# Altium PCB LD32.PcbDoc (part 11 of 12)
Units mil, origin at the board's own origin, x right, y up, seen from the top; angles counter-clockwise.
Board outline 7007.87 x 4368.85 mil, 12 copper layers (Top Layer, Int1 (GND), Int2 (AVDD), Int3 (DVDD), Int4 (GND), Int5 (ST), Int6 (SB), Int8 (AGND), Int7 (AVCC), Int9 (VCCA), Int10 (GND), Bottom Layer), stack 60.136 mil thick; 1165 components, 667 nets, 3910 pads, 2570 vias.
Unrouted connection lines stored in the file: 14.
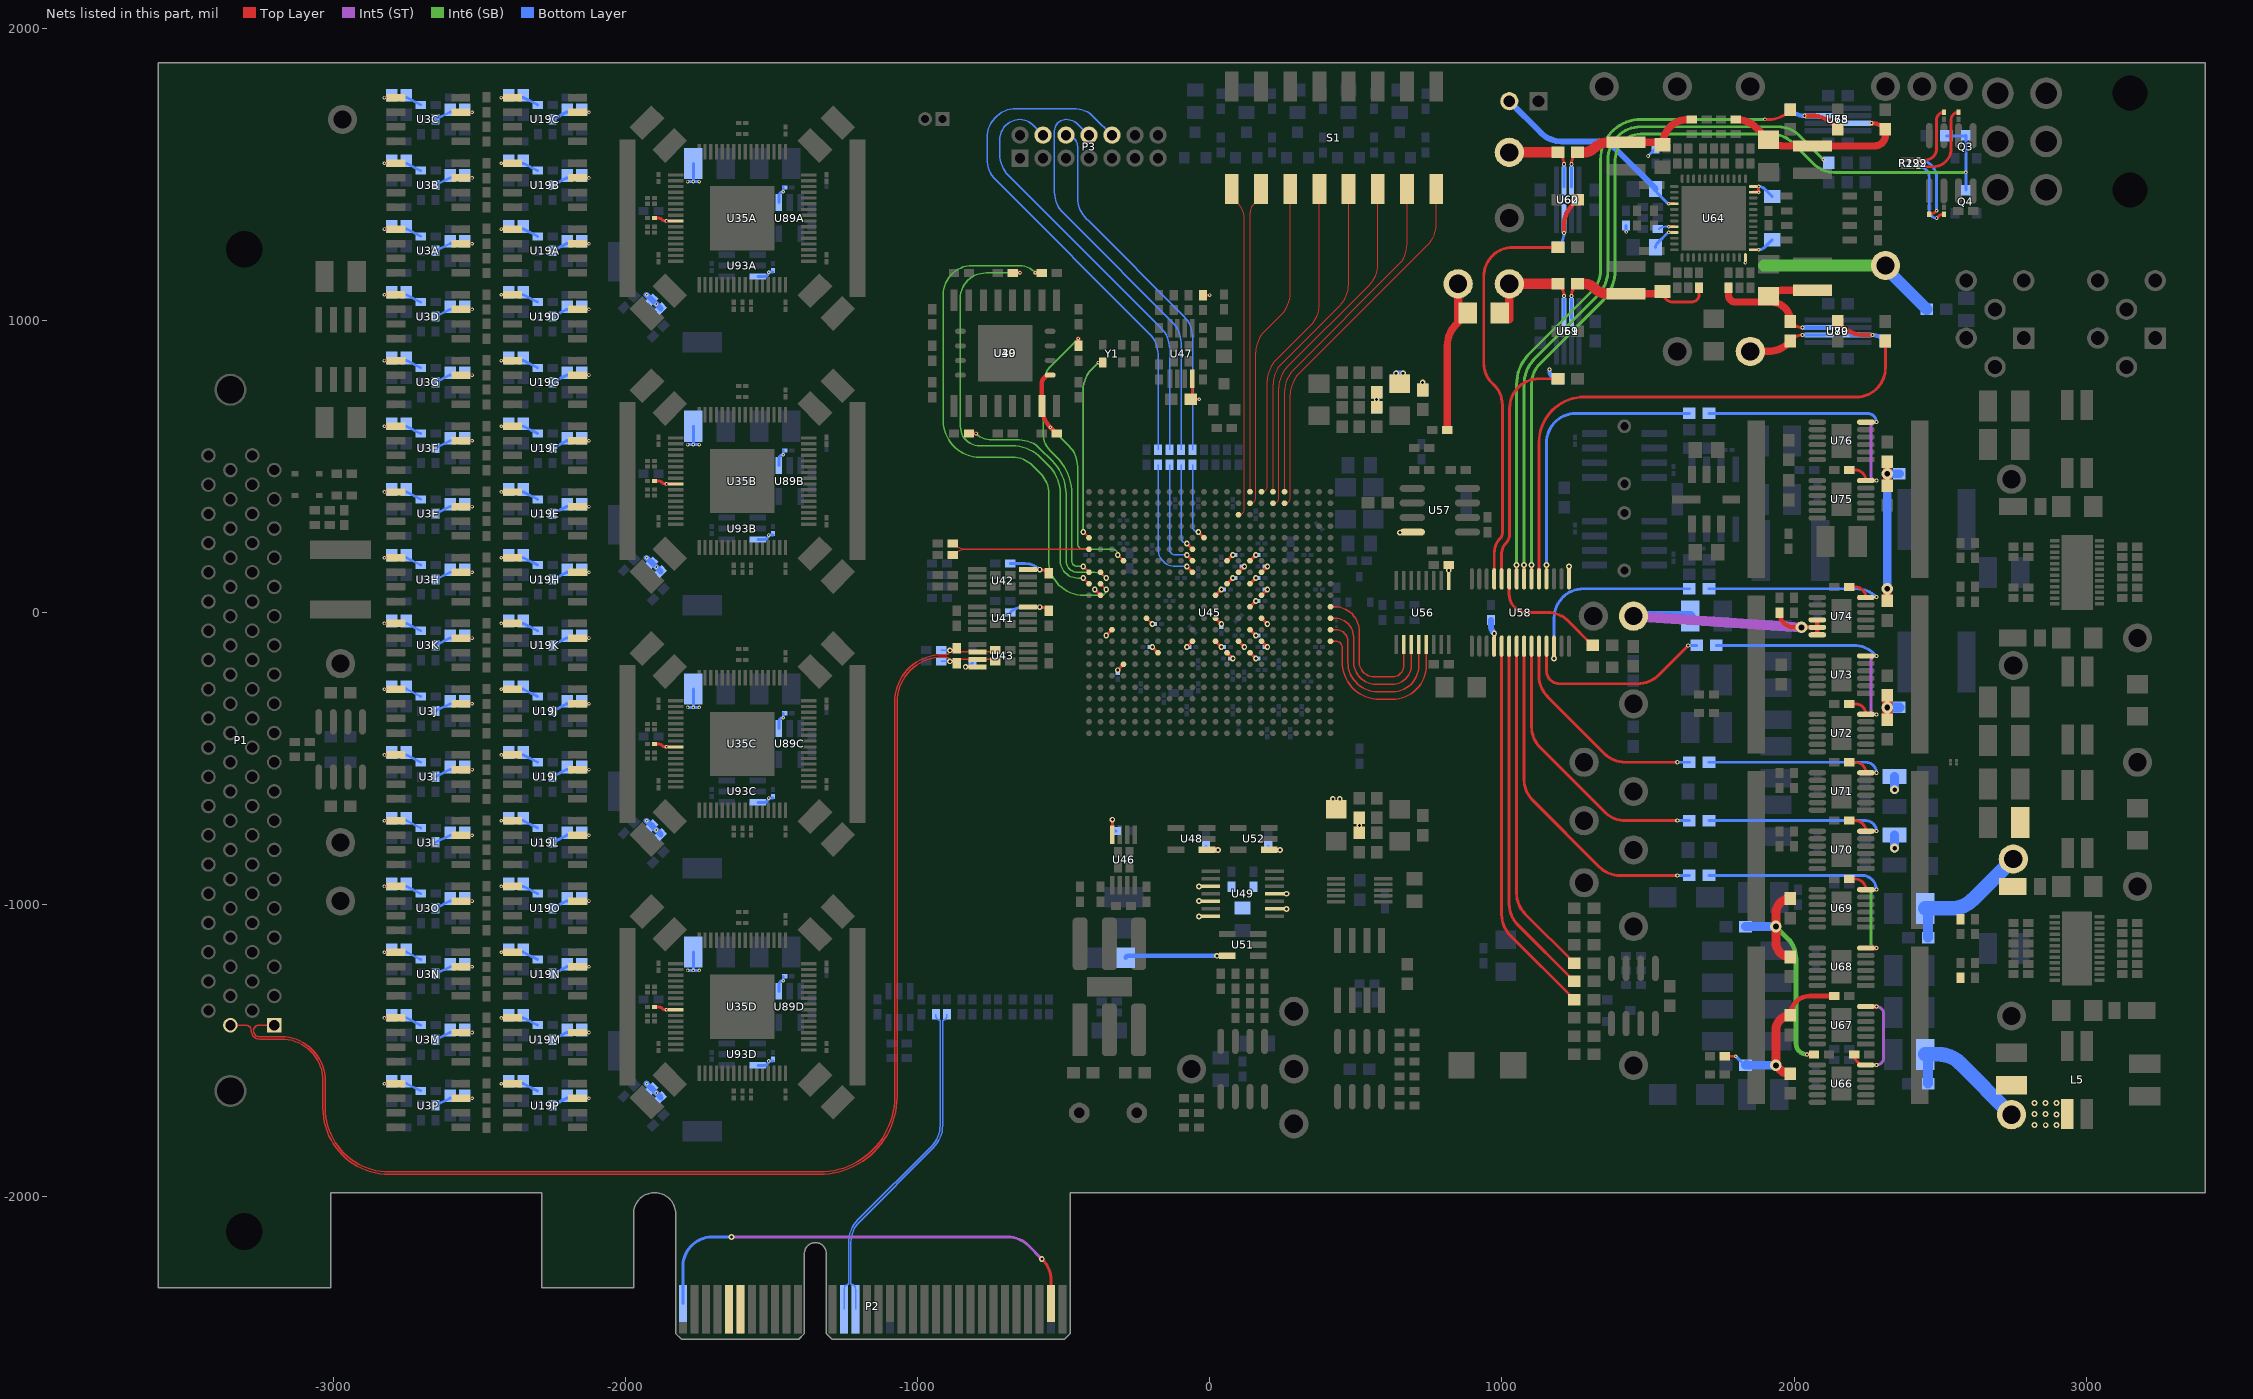
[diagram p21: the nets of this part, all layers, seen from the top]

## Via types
v1: diameter 12, hole 6, Top Layer to Bottom Layer, tented both sides, 1500 vias
v2: diameter 19, hole 10, Top Layer to Bottom Layer, tented both sides, 404 vias
v3: diameter 20, hole 10, Top Layer to Bottom Layer, tented both sides, 337 vias
v4: diameter 14, hole 7, Top Layer to Bottom Layer, tented both sides, 212 vias
v5: diameter 30, hole 15, Top Layer to Bottom Layer, tented both sides, 37 vias
v6: diameter 19.68, hole 7.87, Top Layer to Bottom Layer, 25 vias
v7: diameter 40, hole 20, Top Layer to Bottom Layer, tented both sides, 16 vias
v8: diameter 19.02, hole 10, Top Layer to Bottom Layer, tented both sides, 10 vias
v9: diameter 40, hole 20, Top Layer to Bottom Layer, 9 vias
v10: diameter 60, hole 40, Top Layer to Bottom Layer, 5 vias
v11: diameter 25, hole 13, Top Layer to Bottom Layer, 4 vias
v12: diameter 50, hole 25, Top Layer to Bottom Layer, tented both sides, 4 vias
v13: diameter 35, hole 20, Top Layer to Bottom Layer, 2 vias
v14: diameter 50, hole 25, Top Layer to Bottom Layer, 2 vias
v15: diameter 63, hole 45, Top Layer to Bottom Layer, 1 vias
v16: diameter 14.02, hole 7.01, Top Layer to Bottom Layer, tented both sides, 1 vias
v17: diameter 60, hole 40, Top Layer to Bottom Layer, tented both sides, 1 vias

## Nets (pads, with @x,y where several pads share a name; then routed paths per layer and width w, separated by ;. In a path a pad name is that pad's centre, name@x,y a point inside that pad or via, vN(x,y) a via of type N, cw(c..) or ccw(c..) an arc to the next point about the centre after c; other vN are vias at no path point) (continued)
PRSNT1#: P2.A1 P2.B31 | length 1601.4
  Top Layer w10: v3(-575,-2212.5) -572.52,-2214.98 cw(c-643.23,-2285.69) -543.23,-2285.69 P2.B31@-543.23,-2365.31
  Int5 (ST) w10: v3(-1637.5,-2137.5) -691.42,-2137.5 cw(c-691.42,-2237.5) -620.71,-2166.79 v3(-575,-2212.5)
  Bottom Layer w10: P2.A1@-1803.07,-2365.31 -1803.07,-2237.5 cw(c-1703.07,-2237.5) -1703.07,-2137.5 v3(-1637.5,-2137.5)
PUDC_B: R70.1 R71.1 U45.U22 | length 524.6
  Top Layer w5: R70.1@-879.92,196.85 cw(c-832.4,149.33) -832.4,216.54 ; R71.1@-879.92,236.22 ccw(c-832.4,283.74) -832.4,216.54 ; U45.U22@-413.39,216.54 -832.4,216.54
QSPI_CS: R85.2 U39.7 U40.1 U45.T19 | length 852.8
  Top Layer w5: v2(-314.96,196.85) U45.T19@-295.28,177.17
  Top Layer w15: U40.1@-546.46,812.5 ccw(c-546.46,783.96) -575,783.96 U39.7@-575,706.4 -575,704.51 ccw(c-475,704.51) v1(-545.71,633.8) R85.2@-524.41,612.5
  Int6 (SB) w5: v1(-545.71,633.8) -482.05,570.14 cw(c-552.76,499.43) -452.76,499.43 -452.76,236.22 ccw(c-433.07,236.22) -433.07,216.54 -334.65,216.54 cw(c-334.65,196.85) v2(-314.96,196.85)
QSPI_DQ0: R83.2 U45.P22 | length 1555
  Top Layer w5: v2(-433.07,118.11) U45.P22@-413.39,98.43
  Top Layer w15: R83.2@-674.41,1162.5 v1(-650,1162.5)
  Int6 (SB) w5: v1(-650,1162.5) -765.97,1162.5 ccw(c-765.97,1074.61) -853.87,1074.61 -853.87,637.33 ccw(c-787.4,637.33) -787.4,570.87 -676.55,570.87 cw(c-676.55,431.5) -578,530.05 -552.63,504.68 cw(c-651.18,406.13) -511.81,406.13 -511.81,177.17 ccw(c-452.76,177.17) -452.76,118.11 v2(-433.07,118.11)
QSPI_DQ1: R89.2 U45.R22 | length 939
  Top Layer w5: v2(-433.07,157.48) U45.R22@-413.39,137.8
  Top Layer w15: R89.2@-450,913.09 v1(-450,937.7)
  Int6 (SB) w5: v1(-450,937.7) -541.58,846.12 ccw(c-470.87,775.41) -570.87,775.41 -570.87,611.81 ccw(c-490.67,611.81) -547.38,555.1 -524.79,532.52 cw(c-651.18,406.13) -472.44,406.13 -472.44,177.17 ccw(c-452.76,177.17) -452.76,157.48 v2(-433.07,157.48)
QSPI_DQ2: R84.2 U45.P21 | length 1864.4
  Top Layer w5: U45.P21@-374.02,98.43 v2(-354.33,78.74)
  Top Layer w15: v1(-597.5,1162.5) R84.2@-575.59,1162.5
  Int6 (SB) w5: v1(-597.5,1162.5) -603.05,1168.05 ccw(c-650,1121.11) -650,1187.5 -812.5,1187.5 ccw(c-812.5,1087.5) -912.5,1087.5 -912.5,656.59 ccw(c-787.4,656.59) -787.4,531.5 -676.55,531.5 cw(c-676.55,431.5) -605.84,502.21 -580.47,476.84 cw(c-651.18,406.13) -551.18,406.13 -551.18,178.5 ccw(c-431.74,178.5) -431.74,59.06 -374.02,59.06 ccw(c-374.02,78.74) v2(-354.33,78.74)
QSPI_DQ3: R72.2 U45.R21 | length 864.3
  Top Layer w5: U45.R21@-374.02,137.8 v2(-354.33,118.11)
  Top Layer w15: R72.2@-824.41,612.5 v1(-800,612.5)
  Int6 (SB) w5: v1(-800,612.5) ccw(c-747.01,665.49) -747.01,590.55 -652.09,590.55 cw(c-652.09,490.55) -581.37,561.26 -538.71,518.6 cw(c-651.18,406.13) -492.13,406.13 -492.13,177.17 ccw(c-452.76,177.17) -452.76,137.8 -413.39,137.8 -401.86,137.8 cw(c-401.86,70.59) v2(-354.33,118.11)
QSPI_EMCLK: U45.V22 Y1.3 | length 1235.8
  Top Layer w5: v2(-433.07,275.59) U45.V22@-413.39,255.91
  Top Layer w10: v1(-381.89,855.32) Y1.3@-367.13,855.32
  Int6 (SB) w5: v2(-433.07,275.59) -433.07,762.71 cw(c-333.07,762.71) -403.78,833.42 v1(-381.89,855.32)
  Bottom Layer w5: v2(-433.07,275.59) -433.07,762.71 cw(c-333.07,762.71) -403.78,833.42 v1(-381.89,855.32)
REFCLK_N: C284.1 P2.A14 | length 1147.6
  Bottom Layer w5: P2.A14@-1212.52,-2385 -1212.52,-2315.51 ccw(c-1228.2,-2315.51) -1228.2,-2299.82 -1228.2,-2155.45 cw(c-1128.2,-2155.45) -1198.92,-2084.74 -946.08,-1831.91 ccw(c-1022.45,-1755.54) -914.45,-1755.54 -914.45,-1395.41 ccw(c-914.45,-1380.96) -900,-1380.96 C284.1@-900,-1375.59
REFCLK_P: C285.1 P2.A13 | length 1147.4
  Bottom Layer w5: P2.A13@-1251.89,-2385 -1251.89,-2315.51 cw(c-1236.2,-2315.51) -1236.2,-2299.82 -1236.2,-2155.45 cw(c-1128.2,-2155.45) -1204.57,-2079.09 -952.34,-1826.85 ccw(c-1023.05,-1756.14) -923.05,-1756.14 -923.05,-1395.41 cw(c-923.05,-1380.96) -937.5,-1380.96 C285.1@-937.5,-1375.59
S1NA: C319A.1 R335A.2 R367A.1 U19A.7 | length 171.8
  Top Layer w10: U19A.7@-2163.78,1262.5 v1(-2125,1262.5)
  Bottom Layer w10: R367A.1@-2250,1237.5 -2249.76,1237.62 R335A.2@-2200,1263.09 ; R335A.2@-2201.72,1263.09 R335A.2@-2200,1263.09 ; v1(-2125,1262.5) -2198.57,1262.5 cw(c-2198.57,1264.52) R335A.2@-2200,1263.09
S1NB: C319B.1 R335B.2 R367B.1 U19B.7 | length 171.8
  Top Layer w10: U19B.7@-2163.78,1487.5 v1(-2125,1487.5)
  Bottom Layer w10: R367B.1@-2250,1462.5 -2249.76,1462.62 R335B.2@-2200,1488.09 ; R335B.2@-2201.72,1488.09 R335B.2@-2200,1488.09 ; v1(-2125,1487.5) -2198.57,1487.5 cw(c-2198.57,1489.52) R335B.2@-2200,1488.09
S1NC: C319C.1 R335C.2 R367C.1 U19C.7 | length 171.8
  Top Layer w10: U19C.7@-2163.78,1712.5 v1(-2125,1712.5)
  Bottom Layer w10: R367C.1@-2250,1687.5 -2249.76,1687.62 R335C.2@-2200,1713.09 ; R335C.2@-2201.72,1713.09 R335C.2@-2200,1713.09 ; v1(-2125,1712.5) -2198.57,1712.5 cw(c-2198.57,1714.52) R335C.2@-2200,1713.09
S1ND: C319D.1 R335D.2 R367D.1 U19D.7 | length 171.8
  Top Layer w10: U19D.7@-2163.78,1037.5 v1(-2125,1037.5)
  Bottom Layer w10: R367D.1@-2250,1012.5 -2249.76,1012.62 R335D.2@-2200,1038.09 ; R335D.2@-2201.72,1038.09 R335D.2@-2200,1038.09 ; v1(-2125,1037.5) -2198.57,1037.5 cw(c-2198.57,1039.52) R335D.2@-2200,1038.09
S1NE: C319E.1 R335E.2 R367E.1 U19E.7 | length 171.8
  Top Layer w10: U19E.7@-2163.78,362.5 v1(-2125,362.5)
  Bottom Layer w10: R367E.1@-2250,337.5 -2249.76,337.62 R335E.2@-2200,363.09 ; R335E.2@-2201.72,363.09 R335E.2@-2200,363.09 ; v1(-2125,362.5) -2198.57,362.5 cw(c-2198.57,364.52) R335E.2@-2200,363.09
S1NF: C319F.1 R335F.2 R367F.1 U19F.7 | length 171.8
  Top Layer w10: U19F.7@-2163.78,587.5 v1(-2125,587.5)
  Bottom Layer w10: R367F.1@-2250,562.5 -2249.76,562.62 R335F.2@-2200,588.09 ; R335F.2@-2201.72,588.09 R335F.2@-2200,588.09 ; v1(-2125,587.5) -2198.57,587.5 cw(c-2198.57,589.52) R335F.2@-2200,588.09
S1NG: C319G.1 R335G.2 R367G.1 U19G.7 | length 171.8
  Top Layer w10: U19G.7@-2163.78,812.5 v1(-2125,812.5)
  Bottom Layer w10: R367G.1@-2250,787.5 -2249.76,787.62 R335G.2@-2200,813.09 ; R335G.2@-2201.72,813.09 R335G.2@-2200,813.09 ; v1(-2125,812.5) -2198.57,812.5 cw(c-2198.57,814.52) R335G.2@-2200,813.09
S1NH: C319H.1 R335H.2 R367H.1 U19H.7 | length 171.8
  Top Layer w10: U19H.7@-2163.78,137.5 v1(-2125,137.5)
  Bottom Layer w10: R367H.1@-2250,112.5 -2249.76,112.62 R335H.2@-2200,138.09 ; R335H.2@-2201.72,138.09 R335H.2@-2200,138.09 ; v1(-2125,137.5) -2198.57,137.5 cw(c-2198.57,139.52) R335H.2@-2200,138.09
S1NI: C319I.1 R335I.2 R367I.1 U19I.7 | length 171.8
  Top Layer w10: U19I.7@-2163.78,-537.5 v1(-2125,-537.5)
  Bottom Layer w10: R367I.1@-2250,-562.5 -2249.76,-562.38 R335I.2@-2200,-536.91 ; R335I.2@-2201.72,-536.91 R335I.2@-2200,-536.91 ; v1(-2125,-537.5) -2198.57,-537.5 cw(c-2198.57,-535.48) R335I.2@-2200,-536.91
S1NJ: C319J.1 R335J.2 R367J.1 U19J.7 | length 171.8
  Top Layer w10: U19J.7@-2163.78,-312.5 v1(-2125,-312.5)
  Bottom Layer w10: R367J.1@-2250,-337.5 -2249.76,-337.38 R335J.2@-2200,-311.91 ; R335J.2@-2201.72,-311.91 R335J.2@-2200,-311.91 ; v1(-2125,-312.5) -2198.57,-312.5 cw(c-2198.57,-310.48) R335J.2@-2200,-311.91
S1NK: C319K.1 R335K.2 R367K.1 U19K.7 | length 171.8
  Top Layer w10: U19K.7@-2163.78,-87.5 v1(-2125,-87.5)
  Bottom Layer w10: R367K.1@-2250,-112.5 -2249.76,-112.38 R335K.2@-2200,-86.91 ; R335K.2@-2201.72,-86.91 R335K.2@-2200,-86.91 ; v1(-2125,-87.5) -2198.57,-87.5 cw(c-2198.57,-85.48) R335K.2@-2200,-86.91
S1NL: C319L.1 R335L.2 R367L.1 U19L.7 | length 171.8
  Top Layer w10: U19L.7@-2163.78,-762.5 v1(-2125,-762.5)
  Bottom Layer w10: R367L.1@-2250,-787.5 -2249.76,-787.38 R335L.2@-2200,-761.91 ; R335L.2@-2201.72,-761.91 R335L.2@-2200,-761.91 ; v1(-2125,-762.5) -2198.57,-762.5 cw(c-2198.57,-760.48) R335L.2@-2200,-761.91
S1NM: C319M.1 R335M.2 R367M.1 U19M.7 | length 171.8
  Top Layer w10: U19M.7@-2163.78,-1437.5 v1(-2125,-1437.5)
  Bottom Layer w10: R367M.1@-2250,-1462.5 -2249.76,-1462.38 R335M.2@-2200,-1436.91 ; R335M.2@-2201.72,-1436.91 R335M.2@-2200,-1436.91 ; v1(-2125,-1437.5) -2198.57,-1437.5 cw(c-2198.57,-1435.48) R335M.2@-2200,-1436.91
S1NN: C319N.1 R335N.2 R367N.1 U19N.7 | length 171.8
  Top Layer w10: U19N.7@-2163.78,-1212.5 v1(-2125,-1212.5)
  Bottom Layer w10: R367N.1@-2250,-1237.5 -2249.76,-1237.38 R335N.2@-2200,-1211.91 ; R335N.2@-2201.72,-1211.91 R335N.2@-2200,-1211.91 ; v1(-2125,-1212.5) -2198.57,-1212.5 cw(c-2198.57,-1210.48) R335N.2@-2200,-1211.91
S1NO: C319O.1 R335O.2 R367O.1 U19O.7 | length 171.8
  Top Layer w10: U19O.7@-2163.78,-987.5 v1(-2125,-987.5)
  Bottom Layer w10: R367O.1@-2250,-1012.5 -2249.76,-1012.38 R335O.2@-2200,-986.91 ; R335O.2@-2201.72,-986.91 R335O.2@-2200,-986.91 ; v1(-2125,-987.5) -2198.57,-987.5 cw(c-2198.57,-985.48) R335O.2@-2200,-986.91
S1NP: C319P.1 R335P.2 R367P.1 U19P.7 | length 171.8
  Top Layer w10: U19P.7@-2163.78,-1662.5 v1(-2125,-1662.5)
  Bottom Layer w10: R367P.1@-2250,-1687.5 -2249.76,-1687.38 R335P.2@-2200,-1661.91 ; R335P.2@-2201.72,-1661.91 R335P.2@-2200,-1661.91 ; v1(-2125,-1662.5) -2198.57,-1662.5 cw(c-2198.57,-1660.48) R335P.2@-2200,-1661.91
S1PA: C383A.1 R351A.1 R383A.2 U19A.1 | length 169.2
  Top Layer w10: v1(-2425,1312.5) U19A.1@-2386.22,1312.5
  Bottom Layer w10: v1(-2425,1312.5) -2350,1312.5 R351A.1@-2300.59,1287.5
S1PB: C383B.1 R351B.1 R383B.2 U19B.1 | length 169.2
  Top Layer w10: v1(-2425,1537.5) U19B.1@-2386.22,1537.5
  Bottom Layer w10: v1(-2425,1537.5) -2350,1537.5 R351B.1@-2300.59,1512.5
S1PC: C383C.1 R351C.1 R383C.2 U19C.1 | length 169.2
  Top Layer w10: v1(-2425,1762.5) U19C.1@-2386.22,1762.5
  Bottom Layer w10: v1(-2425,1762.5) -2350,1762.5 R351C.1@-2300.59,1737.5
S1PD: C383D.1 R351D.1 R383D.2 U19D.1 | length 169.2
  Top Layer w10: v1(-2425,1087.5) U19D.1@-2386.22,1087.5
  Bottom Layer w10: v1(-2425,1087.5) -2350,1087.5 R351D.1@-2300.59,1062.5
S1PE: C383E.1 R351E.1 R383E.2 U19E.1 | length 169.2
  Top Layer w10: v1(-2425,412.5) U19E.1@-2386.22,412.5
  Bottom Layer w10: v1(-2425,412.5) -2350,412.5 R351E.1@-2300.59,387.5
S1PF: C383F.1 R351F.1 R383F.2 U19F.1 | length 169.2
  Top Layer w10: v1(-2425,637.5) U19F.1@-2386.22,637.5
  Bottom Layer w10: v1(-2425,637.5) -2350,637.5 R351F.1@-2300.59,612.5
S1PG: C383G.1 R351G.1 R383G.2 U19G.1 | length 169.2
  Top Layer w10: v1(-2425,862.5) U19G.1@-2386.22,862.5
  Bottom Layer w10: v1(-2425,862.5) -2350,862.5 R351G.1@-2300.59,837.5
S1PH: C383H.1 R351H.1 R383H.2 U19H.1 | length 169.2
  Top Layer w10: v1(-2425,187.5) U19H.1@-2386.22,187.5
  Bottom Layer w10: v1(-2425,187.5) -2350,187.5 R351H.1@-2300.59,162.5
S1PI: C383I.1 R351I.1 R383I.2 U19I.1 | length 169.2
  Top Layer w10: v1(-2425,-487.5) U19I.1@-2386.22,-487.5
  Bottom Layer w10: v1(-2425,-487.5) -2350,-487.5 R351I.1@-2300.59,-512.5
S1PJ: C383J.1 R351J.1 R383J.2 U19J.1 | length 169.2
  Top Layer w10: v1(-2425,-262.5) U19J.1@-2386.22,-262.5
  Bottom Layer w10: v1(-2425,-262.5) -2350,-262.5 R351J.1@-2300.59,-287.5
S1PK: C383K.1 R351K.1 R383K.2 U19K.1 | length 169.2
  Top Layer w10: v1(-2425,-37.5) U19K.1@-2386.22,-37.5
  Bottom Layer w10: v1(-2425,-37.5) -2350,-37.5 R351K.1@-2300.59,-62.5
S1PL: C383L.1 R351L.1 R383L.2 U19L.1 | length 169.2
  Top Layer w10: v1(-2425,-712.5) U19L.1@-2386.22,-712.5
  Bottom Layer w10: v1(-2425,-712.5) -2350,-712.5 R351L.1@-2300.59,-737.5
S1PM: C383M.1 R351M.1 R383M.2 U19M.1 | length 169.2
  Top Layer w10: v1(-2425,-1387.5) U19M.1@-2386.22,-1387.5
  Bottom Layer w10: v1(-2425,-1387.5) -2350,-1387.5 R351M.1@-2300.59,-1412.5
S1PN: C383N.1 R351N.1 R383N.2 U19N.1 | length 169.2
  Top Layer w10: v1(-2425,-1162.5) U19N.1@-2386.22,-1162.5
  Bottom Layer w10: v1(-2425,-1162.5) -2350,-1162.5 R351N.1@-2300.59,-1187.5
S1PO: C383O.1 R351O.1 R383O.2 U19O.1 | length 169.2
  Top Layer w10: v1(-2425,-937.5) U19O.1@-2386.22,-937.5
  Bottom Layer w10: v1(-2425,-937.5) -2350,-937.5 R351O.1@-2300.59,-962.5
S1PP: C383P.1 R351P.1 R383P.2 U19P.1 | length 169.2
  Top Layer w10: v1(-2425,-1612.5) U19P.1@-2386.22,-1612.5
  Bottom Layer w10: v1(-2425,-1612.5) -2350,-1612.5 R351P.1@-2300.59,-1637.5
S2NA: C399A.1 R399A.2 R431A.1 U3A.7 | length 169.7
  Top Layer w9: U3A.7@-2563.78,1262.5 v1(-2525,1262.5)
  Bottom Layer w9: R431A.1@-2650,1238.09 R399A.2@-2600,1263.09 ; R399A.2@-2600,1262.5 v1(-2525,1262.5)
S2NB: C399B.1 R399B.2 R431B.1 U3B.7 | length 169.7
  Top Layer w9: U3B.7@-2563.78,1487.5 v1(-2525,1487.5)
  Bottom Layer w9: R431B.1@-2650,1463.09 R399B.2@-2600,1488.09 ; R399B.2@-2600,1487.5 v1(-2525,1487.5)
S2NC: C399C.1 R399C.2 R431C.1 U3C.7 | length 169.7
  Top Layer w9: U3C.7@-2563.78,1712.5 v1(-2525,1712.5)
  Bottom Layer w9: R431C.1@-2650,1688.09 R399C.2@-2600,1713.09 ; R399C.2@-2600,1712.5 v1(-2525,1712.5)
S2ND: C399D.1 R399D.2 R431D.1 U3D.7 | length 169.7
  Top Layer w9: U3D.7@-2563.78,1037.5 v1(-2525,1037.5)
  Bottom Layer w9: R431D.1@-2650,1013.09 R399D.2@-2600,1038.09 ; R399D.2@-2600,1037.5 v1(-2525,1037.5)
S2NE: C399E.1 R399E.2 R431E.1 U3E.7 | length 169.7
  Top Layer w9: U3E.7@-2563.78,362.5 v1(-2525,362.5)
  Bottom Layer w9: R431E.1@-2650,338.09 R399E.2@-2600,363.09 ; R399E.2@-2600,362.5 v1(-2525,362.5)
S2NF: C399F.1 R399F.2 R431F.1 U3F.7 | length 169.7
  Top Layer w9: U3F.7@-2563.78,587.5 v1(-2525,587.5)
  Bottom Layer w9: R431F.1@-2650,563.09 R399F.2@-2600,588.09 ; R399F.2@-2600,587.5 v1(-2525,587.5)
S2NG: C399G.1 R399G.2 R431G.1 U3G.7 | length 169.7
  Top Layer w9: U3G.7@-2563.78,812.5 v1(-2525,812.5)
  Bottom Layer w9: R431G.1@-2650,788.09 R399G.2@-2600,813.09 ; R399G.2@-2600,812.5 v1(-2525,812.5)
S2NH: C399H.1 R399H.2 R431H.1 U3H.7 | length 169.7
  Top Layer w9: U3H.7@-2563.78,137.5 v1(-2525,137.5)
  Bottom Layer w9: R431H.1@-2650,113.09 R399H.2@-2600,138.09 ; R399H.2@-2600,137.5 v1(-2525,137.5)
S2NI: C399I.1 R399I.2 R431I.1 U3I.7 | length 169.7
  Top Layer w9: U3I.7@-2563.78,-537.5 v1(-2525,-537.5)
  Bottom Layer w9: R431I.1@-2650,-561.91 R399I.2@-2600,-536.91 ; R399I.2@-2600,-537.5 v1(-2525,-537.5)
S2NJ: C399J.1 R399J.2 R431J.1 U3J.7 | length 169.7
  Top Layer w9: U3J.7@-2563.78,-312.5 v1(-2525,-312.5)
  Bottom Layer w9: R431J.1@-2650,-336.91 R399J.2@-2600,-311.91 ; R399J.2@-2600,-312.5 v1(-2525,-312.5)
S2NK: C399K.1 R399K.2 R431K.1 U3K.7 | length 169.7
  Top Layer w9: U3K.7@-2563.78,-87.5 v1(-2525,-87.5)
  Bottom Layer w9: R431K.1@-2650,-111.91 R399K.2@-2600,-86.91 ; R399K.2@-2600,-87.5 v1(-2525,-87.5)
S2NL: C399L.1 R399L.2 R431L.1 U3L.7 | length 169.7
  Top Layer w9: U3L.7@-2563.78,-762.5 v1(-2525,-762.5)
  Bottom Layer w9: R431L.1@-2650,-786.91 R399L.2@-2600,-761.91 ; R399L.2@-2600,-762.5 v1(-2525,-762.5)
S2NM: C399M.1 R399M.2 R431M.1 U3M.7 | length 169.7
  Top Layer w9: U3M.7@-2563.78,-1437.5 v1(-2525,-1437.5)
  Bottom Layer w9: R431M.1@-2650,-1461.91 R399M.2@-2600,-1436.91 ; R399M.2@-2600,-1437.5 v1(-2525,-1437.5)
S2NN: C399N.1 R399N.2 R431N.1 U3N.7 | length 169.7
  Top Layer w9: U3N.7@-2563.78,-1212.5 v1(-2525,-1212.5)
  Bottom Layer w9: R431N.1@-2650,-1236.91 R399N.2@-2600,-1211.91 ; R399N.2@-2600,-1212.5 v1(-2525,-1212.5)
S2NO: C399O.1 R399O.2 R431O.1 U3O.7 | length 169.7
  Top Layer w9: U3O.7@-2563.78,-987.5 v1(-2525,-987.5)
  Bottom Layer w9: R431O.1@-2650,-1011.91 R399O.2@-2600,-986.91 ; R399O.2@-2600,-987.5 v1(-2525,-987.5)
S2NP: C399P.1 R399P.2 R431P.1 U3P.7 | length 169.7
  Top Layer w9: U3P.7@-2563.78,-1662.5 v1(-2525,-1662.5)
  Bottom Layer w9: R431P.1@-2650,-1686.91 R399P.2@-2600,-1661.91 ; R399P.2@-2600,-1662.5 v1(-2525,-1662.5)
S2PA: C463A.1 R415A.1 R447A.2 U3A.1 | length 169.4
  Top Layer w9: v1(-2825,1312.5) U3A.1@-2786.22,1312.5
  Bottom Layer w9: v1(-2825,1312.5) R447A.2@-2750,1312.5 ; R447A.2@-2750,1313.09 R415A.1@-2700.59,1287.5
S2PB: C463B.1 R415B.1 R447B.2 U3B.1 | length 169.4
  Top Layer w9: v1(-2825,1537.5) U3B.1@-2786.22,1537.5
  Bottom Layer w9: v1(-2825,1537.5) R447B.2@-2750,1537.5 ; R447B.2@-2750,1538.09 R415B.1@-2700.59,1512.5
S2PC: C463C.1 R415C.1 R447C.2 U3C.1 | length 169.4
  Top Layer w9: v1(-2825,1762.5) U3C.1@-2786.22,1762.5
  Bottom Layer w9: v1(-2825,1762.5) R447C.2@-2750,1762.5 ; R447C.2@-2750,1763.09 R415C.1@-2700.59,1737.5
S2PD: C463D.1 R415D.1 R447D.2 U3D.1 | length 169.4
  Top Layer w9: v1(-2825,1087.5) U3D.1@-2786.22,1087.5
  Bottom Layer w9: v1(-2825,1087.5) R447D.2@-2750,1087.5 ; R447D.2@-2750,1088.09 R415D.1@-2700.59,1062.5
S2PE: C463E.1 R415E.1 R447E.2 U3E.1 | length 169.4
  Top Layer w9: v1(-2825,412.5) U3E.1@-2786.22,412.5
  Bottom Layer w9: v1(-2825,412.5) R447E.2@-2750,412.5 ; R447E.2@-2750,413.09 R415E.1@-2700.59,387.5
S2PF: C463F.1 R415F.1 R447F.2 U3F.1 | length 169.4
  Top Layer w9: v1(-2825,637.5) U3F.1@-2786.22,637.5
  Bottom Layer w9: v1(-2825,637.5) R447F.2@-2750,637.5 ; R447F.2@-2750,638.09 R415F.1@-2700.59,612.5
S2PG: C463G.1 R415G.1 R447G.2 U3G.1 | length 169.4
  Top Layer w9: v1(-2825,862.5) U3G.1@-2786.22,862.5
  Bottom Layer w9: v1(-2825,862.5) R447G.2@-2750,862.5 ; R447G.2@-2750,863.09 R415G.1@-2700.59,837.5
S2PH: C463H.1 R415H.1 R447H.2 U3H.1 | length 169.4
  Top Layer w9: v1(-2825,187.5) U3H.1@-2786.22,187.5
  Bottom Layer w9: v1(-2825,187.5) R447H.2@-2750,187.5 ; R447H.2@-2750,188.09 R415H.1@-2700.59,162.5
S2PI: C463I.1 R415I.1 R447I.2 U3I.1 | length 169.4
  Top Layer w9: v1(-2825,-487.5) U3I.1@-2786.22,-487.5
  Bottom Layer w9: v1(-2825,-487.5) R447I.2@-2750,-487.5 ; R447I.2@-2750,-486.91 R415I.1@-2700.59,-512.5
S2PJ: C463J.1 R415J.1 R447J.2 U3J.1 | length 169.4
  Top Layer w9: v1(-2825,-262.5) U3J.1@-2786.22,-262.5
  Bottom Layer w9: v1(-2825,-262.5) R447J.2@-2750,-262.5 ; R447J.2@-2750,-261.91 R415J.1@-2700.59,-287.5
S2PK: C463K.1 R415K.1 R447K.2 U3K.1 | length 169.4
  Top Layer w9: v1(-2825,-37.5) U3K.1@-2786.22,-37.5
  Bottom Layer w9: v1(-2825,-37.5) R447K.2@-2750,-37.5 ; R447K.2@-2750,-36.91 R415K.1@-2700.59,-62.5
S2PL: C463L.1 R415L.1 R447L.2 U3L.1 | length 169.4
  Top Layer w9: v1(-2825,-712.5) U3L.1@-2786.22,-712.5
  Bottom Layer w9: v1(-2825,-712.5) R447L.2@-2750,-712.5 ; R447L.2@-2750,-711.91 R415L.1@-2700.59,-737.5
S2PM: C463M.1 R415M.1 R447M.2 U3M.1 | length 169.4
  Top Layer w9: v1(-2825,-1387.5) U3M.1@-2786.22,-1387.5
  Bottom Layer w9: v1(-2825,-1387.5) R447M.2@-2750,-1387.5 ; R447M.2@-2750,-1386.91 R415M.1@-2700.59,-1412.5
S2PN: C463N.1 R415N.1 R447N.2 U3N.1 | length 169.4
  Top Layer w9: v1(-2825,-1162.5) U3N.1@-2786.22,-1162.5
  Bottom Layer w9: v1(-2825,-1162.5) R447N.2@-2750,-1162.5 ; R447N.2@-2750,-1161.91 R415N.1@-2700.59,-1187.5
S2PO: C463O.1 R415O.1 R447O.2 U3O.1 | length 169.4
  Top Layer w9: v1(-2825,-937.5) U3O.1@-2786.22,-937.5
  Bottom Layer w9: v1(-2825,-937.5) R447O.2@-2750,-937.5 ; R447O.2@-2750,-936.91 R415O.1@-2700.59,-962.5
S2PP: C463P.1 R415P.1 R447P.2 U3P.1 | length 169.4
  Top Layer w9: v1(-2825,-1612.5) U3P.1@-2786.22,-1612.5
  Bottom Layer w9: v1(-2825,-1612.5) R447P.2@-2750,-1612.5 ; R447P.2@-2750,-1611.91 R415P.1@-2700.59,-1637.5
SENS1: R131.2 U58.19 | length 1308.6
  Top Layer w10: U58.19@999.02,-115.16 999.02,-1034.81 ccw(c1099.02,-1034.81) 1028.31,-1105.52 R131.2@1247.79,-1325
SENS2: R132.2 U58.20 | length 1235.5
  Top Layer w10: U58.20@1024.61,-115.16 1024.61,-997.9 ccw(c1124.61,-997.9) 1053.9,-1068.61 R132.2@1247.79,-1262.5
SENS3: R133.2 U58.21 | length 1162.7
  Top Layer w10: U58.21@1050.2,-115.16 1050,-115.16 1050,-960.79 ccw(c1150,-960.79) 1079.29,-1031.5 R133.2@1247.79,-1200
SENS4: R257.2 U58.22 | length 1174.1
  Top Layer w10: U58.22@1075.79,-115.16 1075.79,-572.01 ccw(c1175.79,-572.01) 1105.08,-642.72 1333.06,-870.71 ccw(c1403.77,-800) 1403.77,-900 v4(1600,-900)
  Bottom Layer w10: v4(1600,-900) R257.2@1641.54,-900
SENS5: R258.2 U58.23 | length 964.9
  Top Layer w10: U58.23@1101.38,-115.16 1101.38,-391.21 ccw(c1201.38,-391.21) 1130.67,-461.92 1351.96,-683.21 ccw(c1422.67,-612.5) 1422.67,-712.5 v4(1600,-712.5)
  Bottom Layer w10: v4(1600,-712.5) R258.2@1641.54,-712.5
SENS6: R259.2 U58.24 | length 754.9
  Top Layer w10: U58.24@1126.97,-115.16 1126.9,-115.16 1126.9,-217.53 ccw(c1226.9,-217.53) 1156.19,-288.24 1351.16,-483.21 ccw(c1421.87,-412.5) 1421.87,-512.5 v4(1600,-512.5)
  Bottom Layer w10: v4(1600,-512.5) R259.2@1641.54,-512.5
SENS7: R253.2 U58.25 | length 673.6
  Top Layer w10: U58.25@1152.56,-115.16 1152.56,-199.46 ccw(c1196.85,-199.46) 1196.85,-243.75 1464.83,-243.75 ccw(c1464.83,-143.75) 1535.54,-214.46 v4(1637.5,-112.5)
  Bottom Layer w10: v4(1637.5,-112.5) R253.2@1666.54,-112.5
SENS8: R254.2 U58.26 | length 701.5
  Top Layer w10: U58.26@1178.15,-115.16 1178.51,-115.16 v3(1178.51,-157.48)
  Bottom Layer w10: v3(1178.51,-157.48) 1178.51,-18.75 cw(c1278.51,-18.75) 1278.51,81.25 R254.2@1641.54,81.25
SENS9: R126.2 U58.11 | length 1371.6
  Top Layer w10: U58.11@973.43,115.16 973.43,203.67 cw(c1045.05,203.67) 994.4,254.32 ccw(c977.73,270.99) 1001.31,270.99 1001.31,711.11 ccw(c906.66,711.11) 973.59,778.04 965.68,785.95 cw(c1033.72,853.98) 937.5,853.98 937.5,1150 cw(c1037.5,1150) 1037.5,1250 R126.2@1191.54,1250
SENS10: R122.2 U58.10 | length 814.5
  Top Layer w10: U58.10@999.02,115.16 999.02,203.67 cw(c1045.05,203.67) 1012.5,236.22 ccw(c979.31,269.42) 1026.25,269.42 1026.25,700 cw(c1126.25,700) 1126.25,800 R122.2@1191.54,800
SENS11: R139.2 U58.9 | length 416.1
  Top Layer w10: U58.9@1024.61,115.16 1024.61,62.89 ccw(c1087.5,62.89) 1087.5,0 1156.36,0 cw(c1156.36,-100) 1227.07,-29.29 R139.2@1310.29,-112.5
SENS12: R161.2 U58.8 | length 2281.1
  Top Layer w10: U58.8@1050.2,115.16 v3(1050.2,162.5) ; v1(1900,1687.5) 1912.61,1687.5 ccw(c1912.61,1787.5) 1983.32,1716.79 R161.2@1987.5,1720.96
  Int6 (SB) w10: v3(1050.2,162.5) 1050.2,780.56 cw(c1200.2,780.56) 1094.13,886.63 1308.21,1100.71 ccw(c1237.5,1171.42) 1337.5,1171.42 1337.5,1550 cw(c1475,1550) 1475,1687.5 v1(1900,1687.5)
SENS13: R235.2 U58.7 | length 2386.9
  Top Layer w10: U58.7@1075.79,115.16 v3(1075.79,162.5)
  Int6 (SB) w10: v3(1075.79,162.5) 1075.79,781.16 cw(c1200.79,781.16) 1112.4,869.54 1325.89,1083.03 ccw(c1237.5,1171.42) 1362.5,1171.42 1362.5,1550 cw(c1475,1550) 1475,1662.5 1946.08,1662.5 cw(c1946.08,1562.5) 2016.79,1633.21 v1(2100,1550)
SENS14: Q3.3 Q4.3 R221.2 U58.6 | length 3092.8
  Top Layer w10: U58.6@1101.38,115.16 v3(1101.38,162.5)
  Int6 (SB) w10: v3(1101.38,162.5) 1101.38,781.75 cw(c1201.38,781.75) 1130.67,852.46 1343.57,1065.36 ccw(c1237.5,1171.42) 1387.5,1171.42 1387.5,1550 cw(c1475,1550) 1475,1637.5 1923.03,1637.5 cw(c1923.03,1537.5) 1993.74,1608.21 2066.24,1535.71 ccw(c2136.95,1606.42) 2136.95,1506.42 v1@2587.5,1506.42
  Bottom Layer w10: R221.2@2520.96,1631.25 2582.99,1631.25 ccw(c2582.99,1637.63) Q3.3@2587.5,1633.12 v1(2587.5,1506.25) Q4.3@2587.5,1445.62
SENS15: R196.2 U58.5 | length 1890.2
  Top Layer w10: U58.5@1126.97,115.16 1126.97,582.96 cw(c1281.5,582.96) 1281.5,737.5 2212.5,737.5 ccw(c2212.5,837.5) 2312.5,837.5 R196.2@2312.5,929.04
SENS16: R255.2 U58.4 | length 1012.1
  Top Layer w10: U58.4@1152.56,115.16 v3(1152.56,162.5)
  Bottom Layer w10: v3(1152.56,162.5) 1152.56,581.25 cw(c1252.56,581.25) 1252.56,681.25 R255.2@1641.54,681.25
SENS_120f_N: C163.1 C164.1 C174.1 C175.1 P4.2 R224.1 TP27.1 U64.4 U64.9 U64.24 U64.25 U64.35 U64.36 | length 1631.3
  Top Layer w10: v1(1571,1300.79) U64.9@1590.16,1300.79 ; v1(1571,1399.21) U64.4@1590.16,1399.21 ; v1(1833.27,1197.36) U64.24@1833.27,1215.16 ; U64.25@1859.84,1241.73 v1(1878.54,1241.73) ; U64.35@1859.84,1438.58 v1(1878.54,1438.58) v1(1878.54,1458.27) U64.36@1859.84,1458.27
  Int6 (SB) w40: 1896.01,1187.5 TP27.1@2312.5,1187.5
  Bottom Layer w10: C174.1@1525.89,1250 cw(c1545.96,1250) 1531.76,1264.19 1566.49,1298.92 cw(c1571,1294.42) v1(1571,1300.79) ; C175.1@1525.89,1450 ccw(c1547.05,1450) 1532.08,1435.04 1565.72,1401.4 ccw(c1571,1406.68) v1(1571,1399.21) ; v1(1878.54,1241.73) ccw(c1878.54,1271.45) 1899.55,1250.44 C163.1@1925,1275.89 ; v1(1878.54,1458.27) cw(c1878.54,1428.55) 1899.54,1449.57 ; 1899.55,1449.56 C164.1@1925,1424.11
  Bottom Layer w20: P4.2@1025,1750 1133.21,1641.79 ccw(c1203.92,1712.5) 1203.92,1612.5 1321.96,1612.5 cw(c1321.96,1512.5) 1392.68,1583.21 C175.1@1525.89,1450
  Bottom Layer w40: TP27.1@2312.5,1187.5 ccw(c2332.7,1187.5) 2318.42,1173.22 R224.1@2454.13,1037.5
SENS_+7_P: R167.1 R168.1 R174.2 R249.2 | length 868.6
  Top Layer w16: v4(2043.75,-1512.5) R174.2@2068.16,-1512.5
  Top Layer w30: R167.1@1987.5,-1179.04 cw(c1987.5,-1129.04) 1937.5,-1129.04 v7(1937.5,-1075) 1937.5,-1029.04 cw(c1987.5,-1029.04) R168.1@1987.5,-979.04
  Int6 (SB) w16: v7(1937.5,-1075) 1976.96,-1114.46 cw(c1906.25,-1185.17) 2006.25,-1185.17 2006.25,-1475 ccw(c2043.75,-1475) v4(2043.75,-1512.5)
  Bottom Layer w30: R249.2@1833.46,-1075 v7(1937.5,-1075)
SENS_-7: R186.2 U66.6 U67.6 | length 360.4
  Top Layer w10: R186.2@2205.66,-1512.5 ccw(c2241.68,-1512.5) 2241.68,-1548.52 U66.6@2245.56,-1548.52 v4(2281.25,-1548.52)
  Top Layer w16: U67.6@2245.56,-1348.52 v4(2281.25,-1348.52)
  Int5 (ST) w10: v4(2281.25,-1548.52) ccw(c2281.25,-1523.52) 2306.25,-1523.52 2306.25,-1373.52 ccw(c2281.25,-1373.52) v4(2281.25,-1348.52)
SENSE.SENS_10_P: C112.1 L3.2 R157.2 R173.2 U79.3 U80.3 | length 601.6
  Top Layer w10: R173.2@1987.5,995.96 1993.25,990.22 ccw(c2029.27,1026.25) v4(2029.27,975.3)
  Top Layer w25: R157.2@1775,1111.91 1775,1087.41 ccw(c1799.91,1087.41) 1799.91,1062.5 C112.1@1892.62,1062.5 ; R173.2@1987.5,995.96 ccw(c1920.96,995.96) 1920.96,1062.5 C112.1@1892.62,1062.5 ; L3.2@2062.5,1103.35 1963.11,1103.35 ccw(c1963.11,1031.77) C112.1@1912.5,1082.38 cw(c1892.62,1082.38) C112.1@1892.62,1062.5
  Bottom Layer w15: v4(2029.27,975.3) U79.3@2062.4,975.3 U80.3@2106.67,975.3
SENSE.SENS_18_P: C113.2 L4.2 R155.2 R189.2 U65.3 U78.3 | length 636.8
  Top Layer w7: R155.2@1800.59,1687.5 R155.2@1801.2,1687.5
  Top Layer w10: R189.2@2310.9,1655.64 R189.2@2312.5,1654.04
  Top Layer w15: v4(2264.86,1674.7) cw(c2264.86,1609.6) R189.2@2310.9,1655.64
  Top Layer w25: R155.2@1801.2,1687.5 cw(c1801.2,1587.5) 1871.91,1658.21 C113.2@1912.5,1617.62 ccw(c1963.11,1668.23) 1963.11,1596.65 L4.2@2062.5,1596.65 2275,1596.65 ccw(c2275,1634.15) 2312.5,1634.15 R189.2@2312.5,1654.04
SENSE.SENS_25_P: C104.2 L2.2 R129.2 R147.2 U60.3 U62.3 | length 579.9
  Top Layer w10: v4(1237.8,1534.3) cw(c1286.16,1534.3) 1251.95,1568.49 R129.2@1258.46,1575
  Top Layer w25: L2.2@1425,1609.15 1541.73,1609.15 cw(c1541.73,1600.89) C104.2@1550,1600.89 cw(c1636.61,1600.89) 1636.61,1687.5 R147.2@1649.41,1687.5
  Top Layer w35: R129.2@1258.46,1575 1280.32,1575 ccw(c1280.32,1626.21) 1316.54,1590 cw(c1362.78,1543.76) 1362.78,1609.15 L2.2@1425,1609.15
  Bottom Layer w10: U62.3@1237.8,1455.83 U60.3@1237.8,1500.1 v4(1237.8,1534.3)
SENSE.SENS_33_P: C103.2 L1.2 R128.2 R153.2 U59.3 U61.3 | length 612.2
  Top Layer w10: v4(1237.8,1083.03) cw(c1289.21,1083.03) 1252.85,1119.39 R128.2@1258.46,1125 ; C103.2@1550,1099.11 ccw(c1586.61,1099.11) 1586.61,1062.5 1648.26,1062.5 ccw(c1648.26,1089.24) 1675,1089.24 R153.2@1675,1111.91
  Top Layer w25: L1.2@1425,1090.85 1530.04,1090.85 ccw(c1530.04,1119.07) C103.2@1550,1099.11
  Top Layer w35: R128.2@1258.46,1125 1280.7,1125 cw(c1280.7,1074.32) 1316.54,1110.16 ccw(c1363.15,1156.78) 1363.15,1090.85 L1.2@1425,1090.85
  Bottom Layer w10: U61.3@1237.8,1005.83 U59.3@1237.8,1050.1 v4(1237.8,1083.03)
SENSE.SENS_120b_N: R197.2 R199.2 | length 221.7
  Top Layer w10: R199.2@2426.31,1549.31 2449.31,1549.31 ccw(c2449.31,1587.5) 2487.5,1587.5 2487.5,1686.94 cw(c2512.5,1686.94) R197.2@2512.5,1711.94
SENSE.SENS_120b_P: R199.3 R200.2 | length 285.2
  Top Layer w10: R199.3@2426.31,1525.69 2475.69,1525.69 ccw(c2475.69,1587.5) 2537.5,1587.5 2537.5,1686.94 cw(c2562.5,1686.94) R200.2@2562.5,1711.94
SENSE.SENS_120x_N: R198.1 R222.3 | length 237.8
  Top Layer w10: R198.1@2462.5,1363.06 ccw(c2462.5,1394.6) 2484.79,1372.29 v1(2487.5,1375)
  Bottom Layer w10: R222.3@2426.31,1549.31 cw(c2426.31,1488.12) 2487.5,1488.12 v1(2487.5,1375)
SENSE.SENS_120x_P: R222.2 R223.1 | length 239.8
  Top Layer w10: v1(2487.5,1350) 2492.12,1354.62 cw(c2512.5,1334.25) R223.1@2512.5,1363.06
  Bottom Layer w10: R222.2@2426.31,1525.69 cw(c2426.31,1489.5) 2462.5,1489.5 2462.5,1375 ccw(c2487.5,1375) v1(2487.5,1350)
SENSE.SENS_+7: R181.2 R257.1 U68.6 U69.6 | length 935.6
  Top Layer w10: R181.2@2188.09,-912.5 2209.54,-912.5 cw(c2209.54,-948.52) U69.6@2245.56,-948.52
  Top Layer w16: U68.6@2245.56,-1148.52 v4(2281.25,-1148.52)
  Int6 (SB) w10: v4(2281.25,-1148.52) cw(c2281.25,-1129.77) 2262.5,-1129.77 2262.5,-967.27 cw(c2281.25,-967.27) v4(2281.25,-948.52)
  Bottom Layer w10: R257.1@1708.46,-900 2232.73,-900 cw(c2232.73,-948.52) v4(2281.25,-948.52)
SENSE.SENS_-7_N: R165.1 R166.1 R180.1 R247.1 R248.2 | length 640.2
  Top Layer w10: R247.1@1763.09,-1518.75 v1(1800,-1518.75)
  Top Layer w16: R166.1@1987.5,-1379.04 cw(c2054.04,-1379.04) 2054.04,-1312.5 R180.1@2136.91,-1312.5
  Top Layer w30: R165.1@1987.5,-1579.04 cw(c1987.5,-1528.42) 1951.71,-1564.21 v7(1937.5,-1550) 1937.5,-1429.04 cw(c1987.5,-1429.04) R166.1@1987.5,-1379.04
  Bottom Layer w10: v1(1800,-1518.75) 1829.68,-1548.43 ccw(c1833.46,-1544.65) R248.2@1833.46,-1550
  Bottom Layer w30: R248.2@1837.5,-1545.96 cw(c1833.46,-1545.96) R248.2@1833.46,-1550 v7(1937.5,-1550)
SENSE.SENS_AVCC: R183.2 R259.1 U71.6 | length 707.1
  Top Layer w10: R183.2@2188.09,-512.5 2209.54,-512.5 cw(c2209.54,-548.52) U71.6@2245.56,-548.52 v4(2281.25,-548.52)
  Bottom Layer w10: R259.1@1708.46,-512.5 2245.23,-512.5 cw(c2245.23,-548.52) v4(2281.25,-548.52)
SENSE.SENS_AVCC3.3V: R179.1 R255.1 U75.6 U76.6 | length 889.2
  Top Layer w10: R179.1@2188.09,487.5 2209.54,487.5 cw(c2209.54,451.48) U75.6@2245.56,451.48
  Int5 (ST) w10: v4(2281.25,451.48) cw(c2281.25,470.23) 2262.5,470.23 2262.5,632.73 cw(c2281.25,632.73) v4(2281.25,651.48)
  Bottom Layer w10: R255.1@1708.46,681.25 2251.48,681.25 cw(c2251.48,651.48) v4(2281.25,651.48)
SENSE.SENS_AVTT: R182.2 R258.1 U70.6 | length 707.6
  Top Layer w10: R182.2@2188.09,-712.5 2209.54,-712.5 cw(c2209.54,-748.52) U70.6@2245.56,-748.52 v4(2281.54,-748.52)
  Bottom Layer w10: R258.1@1708.46,-712.5 2245.51,-712.5 cw(c2245.51,-748.52) v4(2281.54,-748.52)
SENSE.SENS_DVDD1.2V: R177.1 R253.1 U72.6 U73.6 | length 857.8
  Top Layer w10: R177.1@2188.09,-312.5 2209.54,-312.5 cw(c2209.54,-348.52) U72.6@2245.56,-348.52
  Int5 (ST) w10: v4(2281.25,-348.52) cw(c2281.25,-329.77) 2262.5,-329.77 2262.5,-167.27 cw(c2281.25,-167.27) v4(2281.25,-148.52)
  Bottom Layer w10: R253.1@1733.46,-112.5 2203.81,-112.5 cw(c2203.81,-212.5) 2274.52,-141.79 v4(2281.25,-148.52)
SENSE.SENS_VCCA3.3V: R178.1 R254.1 U74.6 | length 658.7
  Top Layer w10: R178.1@2188.09,87.5 2209.54,87.5 cw(c2209.54,51.48) U74.6@2245.56,51.48
  Bottom Layer w10: R254.1@1708.46,81.25 2213.14,81.25 cw(c2213.14,-15.48) v4(2281.54,52.92)
SMCLK: P2.B5
SMDAT: P2.B6
SQSPI.XMUX0: U45.K1 U56.12 | length 576.9
  Top Layer w5: U45.K1@413.39,-59.06 433.07,-59.06 cw(c433.07,-98.43) 472.44,-98.43 472.44,-169.29 ccw(c574.59,-169.29) 574.59,-271.44 624.34,-271.44 ccw(c624.34,-180.23) 715.55,-180.23 U56.12@715.55,-109.25
SQSPI.XMUX1: U45.L1 U56.11 | length 550.6
  Top Layer w5: U45.L1@413.39,-19.68 427.44,-19.68 cw(c427.44,-84.37) 492.13,-84.37 492.13,-169.29 ccw(c568.69,-169.29) 568.69,-245.85 624.34,-245.85 ccw(c624.34,-180.23) 689.96,-180.23 U56.11@689.96,-109.25
SQSPI.XMUX2: U45.M1 U56.10 | length 526.7
  Top Layer w5: U45.M1@413.39,19.69 427.5,19.69 cw(c427.5,-64.63) 511.81,-64.63 511.81,-169.29 ccw(c562.78,-169.29) 562.78,-220.26 624.34,-220.26 ccw(c624.34,-180.23) 664.37,-180.23 U56.10@664.37,-109.25
SQSPI.XMUX3: U45.J1 U56.13 | length 600.7
  Top Layer w5: U45.J1@413.39,-98.43 433.07,-98.43 cw(c433.07,-118.11) 452.76,-118.11 452.76,-169.29 ccw(c580.5,-169.29) 580.5,-297.03 624.34,-297.03 ccw(c624.34,-180.23) 741.14,-180.23 U56.13@741.14,-109.25
SW1: S1.16 U45.AA5 | length 1285.3
  Top Layer w4.2: U45.AA5@255.91,374.02 ccw(c255.91,393.7) 275.59,393.7 275.59,746.67 cw(c375.59,746.67) 304.88,817.38 745.71,1258.21 ccw(c675,1328.92) 775,1328.92 S1.16@775,1449.8
SW2: S1.15 U45.AB5 | length 1201.4
  Top Layer w4.2: U45.AB5@255.91,413.39 255.91,472.44 255.91,758.23 cw(c355.91,758.23) 285.19,828.94 645.71,1189.46 ccw(c575,1260.17) 675,1260.17 S1.15@675,1449.8
SW3: S1.14 U45.AA6 | length 1218.7
  Top Layer w4.2: U45.AA6@216.54,374.02 ccw(c216.54,393.7) 236.22,393.7 236.22,769.8 cw(c336.22,769.8) 265.51,840.51 545.71,1120.71 ccw(c475,1191.42) 575,1191.42 S1.14@575,1449.8
SW4: S1.13 U45.AB6 | length 1134.9
  Top Layer w4.2: U45.AB6@216.54,413.39 216.54,472.44 216.54,781.36 cw(c316.54,781.36) 245.82,852.07 445.71,1051.96 ccw(c375,1122.67) 475,1122.67 S1.13@475,1449.8
SW5: S1.12 U45.AB7 | length 1112.8
  Top Layer w4.2: U45.AB7@177.17,413.39 ccw(c177.17,433.07) 196.85,433.07 196.85,792.93 cw(c296.85,792.93) 226.14,863.64 345.71,983.21 ccw(c275,1053.92) 375,1053.92 S1.12@375,1449.8
SW6: S1.11 U45.AA8 | length 1127.1
  Top Layer w4.2: U45.AA8@137.8,374.02 ccw(c137.8,393.7) 157.48,393.7 157.48,891.06 cw(c257.48,891.06) 186.77,961.77 245.71,1020.71 ccw(c175,1091.42) 275,1091.42 S1.11@275,1449.8
SW7: S1.10 U45.AB8 | length 1047.2
  Top Layer w4.2: U45.AB8@137.8,413.39 137.8,1368.04 cw(c179.46,1368.04) 150,1397.5 155.69,1403.19 ccw(c109.08,1449.8) S1.10@175,1449.8
SW8: S1.9 U45.Y9 | length 1138.4
  Top Layer w4.2: S1.9@75,1449.8 ccw(c144.72,1449.8) 95.42,1400.51 98.43,1397.5 cw(c50.9,1349.98) 118.11,1349.98 118.11,354.33 cw(c98.43,354.33) U45.Y9@98.43,334.65
SW+2V: L9.1 L10.1 R190.2 R191.2 R227.1 | length 214.5
  Top Layer w35: R190.2@2318.75,-366.54 v7(2318.75,-325) R191.2@2318.75,-283.46
  Bottom Layer w30: v5(2343.75,-806.25) L9.1@2343.75,-761.32 ; v5(2343.75,-606.25) L10.1@2343.75,-561.32
  Bottom Layer w35: v7(2318.75,-325) R227.1@2360.29,-325
SW+4V: R192.2 R193.2 R194.2 R228.1 | length 559.9
  Top Layer w30: R192.2@2318.75,39.71 v7(2318.75,81.25) ; R193.2@2318.75,433.46 v7(2318.75,475) R194.2@2318.75,516.54
  Bottom Layer w30: v7(2318.75,81.25) v7(2318.75,475) R228.1@2360.29,475
SW+10V: C122.2 C151.1 D4.2 R202.2 R226.2 TP34.1 | length 469.3
  Bottom Layer w35: C151.1@2448.87,-1012.5 cw(c2425.7,-1035.67) 2458.46,-1035.67 R226.2@2458.46,-1112.5
  Bottom Layer w50: C151.1@2448.87,-1012.5 2539.83,-1012.5 ccw(c2539.83,-912.5) 2610.54,-983.21 TP34.1@2750,-843.75
SW-10V: C128.1 C150.2 L5.3 R201.1 R225.2 TP31.1 | length 478.6
  Bottom Layer w35: C150.2@2448.87,-1512.5 cw(c2425.7,-1535.67) 2458.46,-1535.67 R225.2@2458.46,-1612.5
  Bottom Layer w50: C150.2@2448.87,-1512.5 2496.08,-1512.5 cw(c2496.08,-1612.5) 2566.79,-1541.79 TP31.1@2743.75,-1718.75
  other v3: 2860.93,-1754.73 2823.06,-1753.87 2898.06,-1753.87 2898.06,-1717.62 2823.06,-1716.37 2860.56,-1716.37 2823.06,-1678.87 2860.56,-1678.87 2898.06,-1678.87
TCK_FPGA: R299.2 U45.V12 | length 269.4
  Top Layer w10: v2(-39.37,275.59) U45.V12@-19.68,255.91
  Bottom Layer w5: R299.2@-59.06,505.91 -59.06,295.28 ccw(c-39.37,295.28) v2(-39.37,275.59)
TCK_JTAG: P3.6 R299.1 | length 1275.1
  Bottom Layer w5: P3.6@-481.31,1623.04 P3.6@-492.13,1633.86 cw(c-492.13,1594.23) -452.5,1594.23 -452.5,1419.12 ccw(c-352.5,1419.12) -423.21,1348.41 -413.39,1338.58 -88.34,1013.54 cw(c-159.06,942.83) -59.06,942.83 ; R299.1@-59.06,557.09 -59.06,942.83 ; -59.06,948.88 -59.06,942.83
TDI_FPGA: R302.2 U45.R13 | length 449.2
  Top Layer w10: v2(-78.74,157.48) U45.R13@-59.05,137.8
  Bottom Layer w5: R302.2@-177.17,505.91 -177.17,216.88 ccw(c-117.77,216.88) -117.77,157.48 v2(-78.74,157.48)
TDI_JTAG: P3.10 R302.1 | length 1820.1
  Bottom Layer w5: P3.10@-334.65,1633.86 -396.5,1695.71 ccw(c-467.21,1625) -467.21,1725 -662.5,1725 ccw(c-662.5,1625) -762.5,1625 -762.5,1551.95 ccw(c-662.5,1551.95) -733.21,1481.24 -206.45,954.49 cw(c-277.17,883.78) -177.17,883.78 R302.1@-177.17,557.09
TDO_FPGA: R300.2 U45.U13 | length 308.8
  Top Layer w10: v2(-78.74,236.22) U45.U13@-59.05,216.54
  Bottom Layer w5: R300.2@-98.43,505.91 -98.43,255.91 ccw(c-78.74,255.91) v2(-78.74,236.22)
TDO_JTAG: P3.8 R300.1 | length 1425
  Bottom Layer w5: P3.8@-413.39,1633.86 -449.49,1669.96 ccw(c-492.13,1627.33) -492.13,1687.62 -492.25,1687.5 -492.32,1687.5 ccw(c-492.32,1648.19) -531.63,1648.19 -531.63,1439.2 ccw(c-431.63,1439.2) -502.34,1368.48 -472.44,1338.58 -127.71,993.86 cw(c-198.43,923.15) -98.43,923.15 ; R300.1@-98.43,557.09 -98.43,923.15 ; -98.43,925.75 -98.43,923.15
TMS_FPGA: R301.2 U45.T13 | length 387.5
  Top Layer w10: v2(-78.74,196.85) U45.T13@-59.05,177.17
  Bottom Layer w5: R301.2@-137.8,505.91 -137.8,216.54 ccw(c-118.11,216.54) -118.11,196.85 v2(-78.74,196.85)
TMS_JTAG: P3.4 R301.1 | length 1500.3
  Bottom Layer w5: P3.4@-570.87,1633.86 -606.76,1669.75 ccw(c-649.61,1626.91) -649.61,1687.5 ccw(c-649.61,1618.36) -718.75,1618.36 -718.75,1567.26 ccw(c-618.75,1567.26) -689.46,1496.55 -167.08,974.17 cw(c-237.8,903.46) -137.8,903.46 R301.1@-137.8,557.09
TRG_N: P1.2 R74.1 R76.2 R314.2 U43.7 | length 4581.6
  Top Layer w5: P1.2@-3352.3,-1412.5 -3300.05,-1412.5 cw(c-3300.05,-1431.25) -3281.3,-1431.25 ccw(c-3252.55,-1431.25) -3252.55,-1460 -3178.2,-1460 cw(c-3178.2,-1602.65) -3035.55,-1602.65 -3035.55,-1696.24 ccw(c-2808.83,-1696.24) -2808.83,-1922.97 -1336.21,-1922.97 ccw(c-1336.21,-1657.21) -1070.46,-1657.21 -1070.46,-306.47 cw(c-916.48,-306.47) -916.48,-152.49 -904.59,-152.49 cw(c-904.59,-167.32) v2(-889.76,-167.32) cw(c-873.13,-183.96) -873.13,-160.43 U43.7@-795.08,-160.43 -750.89,-160.43 cw(c-750.89,-183.96) R76.2@-734.25,-167.32
  Bottom Layer w5: R314.2@-919.29,-167.32 v2(-889.76,-167.32)
TRG_P: P1.1 R74.2 R77.2 R315.1 U43.6 | length 4569
  Top Layer w5: P1.1@-3202.3,-1412.5 -3254.55,-1412.5 ccw(c-3254.55,-1431.25) -3273.3,-1431.25 ccw(c-3252.55,-1431.25) -3252.55,-1452 -3178.2,-1452 cw(c-3178.2,-1602.65) -3027.55,-1602.65 -3027.55,-1696.24 ccw(c-2808.83,-1696.24) -2808.83,-1914.97 -1336.21,-1914.97 ccw(c-1336.21,-1657.21) -1078.46,-1657.21 -1078.46,-306.47 cw(c-916.48,-306.47) -916.48,-144.49 -904.59,-144.49 ccw(c-904.59,-129.66) v2(-889.76,-129.66) ccw(c-877.26,-117.16) -877.26,-134.84 U43.6@-795.08,-134.84 -750.89,-134.84 ccw(c-750.89,-111.32) R77.2@-734.25,-127.95
  Bottom Layer w5: R315.1@-919.29,-127.95 ccw(c-915.16,-123.82) -915.16,-129.66 v2(-889.76,-129.66)
VCC: C62.2 C63.2 C65.2 C152.1 C155.1 C179.1 C217.2 C230.2 C232.1 C245.2 C249.2 C266.2 C281.2 FR2.1 FR9.2 R106.1 R123.1 R127.1 R128.1 R169.1 R195.1 R278.2 R308.1 R310.1 TP9.1 U41.8 U42.8 U43.8 U46.8 U47.8 U48.1 U49.2 U49.4 U49.10 U49.12 U49.14 U51.5 U52.1 U59.2 U60.7 U61.2 U62.7 U65.7 U78.7 U79.7 U80.7 | length 2266.4
  Top Layer w8: U47.8@-60.04,799.41 -60.04,729.58 v1(-35.93,729.58) ; R106.1@-23.43,1086.42 v1(0,1086.42)
  Top Layer w10: v2(-835.96,-186.02) U43.8@-795.08,-186.02 ; U41.8@-622.24,18.7 v2(-582.07,18.7) cw(c-582.07,-24.98) C63.2@-551.18,5.91 ; U42.8@-622.24,146.65 v2(-582.07,146.65) cw(c-582.07,102.97) C62.2@-551.18,133.86 ; U46.8@-333.66,-760.04 v2(-333.66,-708.66) ; R128.1@1191.54,1125 1197.14,1119.39 cw(c1160.79,1083.03) v4(1212.2,1083.03)
  Top Layer w15: v4(1212.2,1299.5) 1212.2,1324.82 cw(c1312.2,1324.82) 1241.49,1395.53 C179.1@1258.46,1412.5 ; v4(2035.61,1700.3) 2062.32,1700.3 cw(c2062.32,1600.3) 2133.03,1671.01 C155.1@2150,1654.04 ; C152.1@2150,995.96 2166.97,978.99 ccw(c2237.68,1049.7) 2237.68,949.7 v4(2268.45,949.7)
  Top Layer w20: U48.1@-9.35,-812.4 -9.35,-812.5 v3(27.5,-812.5)
  Top Layer w30: 1025,1004.83 TP9.1@1025,1125
  Top Layer w35: TP9.1@1025,1125 R128.1@1191.54,1125
  Bottom Layer w10: v2(-835.96,-186.02) ccw(c-835.96,-160.99) -818.26,-178.7 C281.2@-812.5,-172.93 ; R308.1@-683.07,0 cw(c-637.92,-45.15) -637.92,18.7 v2(-582.07,18.7) ; R310.1@-683.07,167.32 -631.97,167.32 cw(c-631.97,96.75) v2(-582.07,146.65) ; v2(-333.66,-708.66) -333.66,-735.24 ccw(c-320.87,-735.24) C266.2@-320.87,-748.03 ; C249.2@-12.5,-800.59 ccw(c-0.59,-800.59) -0.59,-812.5 v3(27.5,-812.5) ; C217.2@200,-800.59 ccw(c211.91,-800.59) 211.91,-812.5 v3(240,-812.5) ; R127.1@1191.54,1250 1191.82,1250.28 ccw(c1142.6,1299.5) v4(1212.2,1299.5) ; U61.2@1212.2,1005.83 U59.2@1212.2,1053.57 ; U59.2@1212.2,1050.1 U59.2@1212.2,1053.45 ; U59.2@1212.2,1059.7 U59.2@1212.2,1053.57 ; v4(1212.2,1083.03) U59.2@1212.2,1053.45 ; v4@1212.2,1293.65 v4(1212.2,1299.5) ; U60.7@1212.2,1324.9 v4(1212.2,1299.5) ; v1(1425,1302.5) R278.2@1425,1324.41 ; U59.2@1212.2,1053.45 ccw(c1141.64,1053.45) U59.2@1212.2,1053.57
  Bottom Layer w15: FR9.2@-287.38,-1181.25 cw(c-281.13,-1181.25) -281.13,-1175 v3(25,-1175) ; v4(1162.5,831.25) 1162.5,829.04 ccw(c1191.54,829.04) R123.1@1191.54,800 ; R169.1@1987.5,1720.96 1988.76,1719.7 ccw(c2035.61,1766.55) v4(2035.61,1700.3) U65.7@2062.4,1700.3 ; U80.7@2193.33,949.7 U79.7@2237.6,949.7 v4(2268.45,949.7) cw(c2268.45,893.27) 2308.36,933.18 R195.1@2312.5,929.04
  other v3: -37.5,-1040 262.5,-1015 -37.5,-987.5 262.5,-962.5 -37.5,-937.5
VCC1V0: C82.2 C83.2 C85.2 C92.2 C183.2 C186.2 C191.2 C192.2 C218.1 C219.1 C221.1 C222.1 C223.1 C224.1 C225.1 C226.1 C235.2 C236.1 C237.1 C242.1 C243.1 C244.2 C246.1 R173.1 R271.2 TP25.1 U45.H8 U45.H10 U45.J7 U45.J9 U45.J11 U45.K8 U45.L7 U45.L11 U45.M8 U45.N7 U45.N11 U45.P8 U45.P10 U45.R7 U45.R9 U45.T8 U45.T10 U79.2 U80.2 | length 908
  Top Layer w10: U45.J11@19.69,-98.43 v2(39.37,-118.11) ; U45.L11@19.69,-19.68 v2(39.37,-39.37) ; U45.N11@19.69,59.06 v2(39.37,78.74) ; U45.H10@59.06,-137.8 v2(78.74,-157.48) ; U45.P10@59.06,98.43 v2(78.74,118.11) ; U45.T10@59.06,177.17 v2(78.74,196.85) ; U45.J9@98.43,-98.43 v2(118.11,-118.11) ; U45.R9@98.43,137.8 v2(118.11,157.48) ; U45.H8@137.8,-137.8 v2(157.48,-157.48) ; U45.K8@137.8,-59.06 v2(157.48,-78.74) ; U45.M8@137.8,19.69 v2(157.48,39.37) ; U45.P8@137.8,98.43 v2(157.48,118.11) ; U45.T8@137.8,177.17 v2(157.48,196.85) ; U45.J7@177.17,-98.43 v2(196.85,-118.11) ; U45.L7@177.17,-19.68 v2(196.85,-39.37) ; U45.N7@177.17,59.06 v2(196.85,78.74) ; U45.R7@177.17,137.8 v2(196.85,157.48) ; C82.2@570.87,702.76 C83.2@570.87,753.94 ; R173.1@1987.5,929.04 1993.25,934.78 cw(c2029.27,898.75) v4(2029.27,949.7)
  Top Layer w25: TP25.1@1850,893.75 1910.79,893.75 ccw(c1910.79,993.75) 1981.5,923.04 R173.1@1987.5,929.04
  Bottom Layer w10: C191.2@570.87,702.76 v2(570.87,728.35) C192.2@570.87,753.94 ; v1(1500,1562.5) R271.2@1525,1587.5 ; v4(2029.27,949.7) U79.2@2062.4,949.7 U80.2@2106.67,949.7
  Bottom Layer w20: v2(637.8,818.9) v2(661.42,818.9)
  other v2: 728.35,787.4
VCC2: C93.1 C95.2 C180.1 FR2.2 TP8.1 U56.1 U57.8 U58.1 U58.18 | length 643.6
  Top Layer w10: U58.1@1229.33,115.16 v3(1229.33,157.48)
  Top Layer w25: C93.1@813.09,625 813.09,914.29 cw(c913.09,914.29) 842.38,985 FR2.2@882.38,1025
  Top Layer w30: 850,997.5 TP8.1@850,1125
  Bottom Layer w20: C180.1@962.5,-25.59 962.5,-45.67 ccw(c999.8,-45.67) v3(973.43,-72.05)
  other v2: 817.8,144.34 650.49,273.5
VCC2V5: C73.2 C76.2 C77.2 C176.2 C255.2 C262.2 C264.2 C271.2 R129.1 TP11.1 U45.G19 U45.H16 U45.J13 U45.K20 U45.L17 U45.N21 U60.2 U62.2 U64.8 | length 513.6
  Top Layer w7.99: U45.L17@-216.54,-19.68 v2(-196.85,-39.37)
  Top Layer w9.65: v2(-354.33,-78.74) U45.K20@-334.65,-59.06
  Top Layer w10: v2(-393.7,78.74) U45.N21@-374.02,59.06 ; v2(-314.96,-196.98) -314.96,-196.91 U45.G19@-295.28,-177.17 U45.G19@-295.28,-177.17 ; v2(-196.85,-118.11) U45.H16@-177.17,-137.8 ; v2(-78.74,-118.11) U45.J13@-59.05,-98.43 ; R129.1@1191.54,1575 1198.04,1568.5 cw(c1163.84,1534.3) v4(1212.2,1534.3) ; v1(1571,1320.47) U64.8@1590.16,1320.47
  Top Layer w35: TP11.1@1025,1575 R129.1@1191.54,1575
  Bottom Layer w7: C176.2@1538.09,1312.5 cw(c1557.34,1293.25) 1557.34,1320.47 v1(1571,1320.47)
  Bottom Layer w10: U62.2@1212.2,1455.83 U60.2@1212.2,1500.1 v4(1212.2,1534.3)
  other v2: 511.81,-728.35 421.26,-637.8 444.88,-637.8
VCCA3.3V: C15A.2 C15B.2 C15C.2 C15D.2 C169.2 C295A.1 C295B.1 C295C.1 C295D.1 C299A.2 C299B.2 C299C.2 C299D.2 C303A.2 C303B.2 C303C.2 C303D.2 R164.1 R323A.2 R323B.2 R323C.2 R323D.2 R331A.2 R331B.2 R331C.2 R331D.2 TP22.1 U35A.25 U35B.25 U35C.25 U35D.25 U74.10 U74.11 U74.12 U89A.1 U89B.1 U89C.1 U89D.1 U93A.6 U93B.6 U93C.6 U93D.6 | length 2422.1
  Top Layer w10: C15D.2@-1895,-1350 -1887.07,-1350 cw(c-1887.07,-1367.07) -1875,-1355 ccw(c-1863.31,-1343.31) -1863.31,-1359.84 v1(-1860,-1359.84) U35D.25@-1827.5,-1359.84 ; C15C.2@-1895,-450 -1887.07,-450 cw(c-1887.07,-467.07) -1875,-455 ccw(c-1863.31,-443.31) -1863.31,-459.84 v1(-1860,-459.84) U35C.25@-1827.5,-459.84 ; C15B.2@-1895,450 -1887.07,450 cw(c-1887.07,432.93) -1875,445 ccw(c-1863.31,456.69) -1863.31,440.16 v1(-1860,440.16) U35B.25@-1827.5,440.16 ; C15A.2@-1895,1350 -1887.07,1350 cw(c-1887.07,1332.93) -1875,1345 ccw(c-1863.31,1356.69) -1863.31,1340.16 v1(-1860,1340.16) U35A.25@-1827.5,1340.16
  Top Layer w15: R164.1@1950,-0.59 ccw(c2000.3,-0.59) 2000.3,-50.89 v7(2025,-50.89) U74.11@2079.44,-50.89 ; U74.12@2079.44,-76.48 U74.11@2079.44,-50.89 ; U74.10@2079.44,-25.3 U74.11@2079.44,-50.89
  Int5 (ST) w35: TP22.1@1450,-12.5 v7(2025,-50.89)
  Bottom Layer w10: v1(-1787.5,-1225) v1(-1767.68,-1225) ; v1(-1787.5,-325) v1(-1767.68,-325) ; v1(-1787.5,575) v1(-1767.68,575) ; v1(-1787.5,1475) v1(-1767.68,1475) ; C303D.2@-1767.62,-1162.5 v1(-1767.68,-1225) ; C303C.2@-1767.62,-262.5 v1(-1767.68,-325) ; C303B.2@-1767.62,637.5 v1(-1767.68,575) ; C303A.2@-1767.62,1537.5 v1(-1767.68,1475) ; v1(-1747.64,-1225) v1(-1767.68,-1225) ; v1(-1747.64,-325) v1(-1767.68,-325) ; v1(-1747.64,575) v1(-1767.68,575) ; v1(-1747.64,1475) v1(-1767.68,1475) ; U93D.6@-1546.85,-1549.9 -1524.9,-1549.9 ccw(c-1524.9,-1535) v1(-1510,-1535) C299D.2@-1495,-1535 ; U93C.6@-1546.85,-649.9 -1524.9,-649.9 ccw(c-1524.9,-635) v1(-1510,-635) C299C.2@-1495,-635 ; U93B.6@-1546.85,250.1 -1524.9,250.1 ccw(c-1524.9,265) v1(-1510,265) C299B.2@-1495,265 ; U93A.6@-1546.85,1150.1 -1524.9,1150.1 ccw(c-1524.9,1165) v1(-1510,1165) C299A.2@-1495,1165 ; U89D.1@-1474.9,-1296.85 -1474.9,-1274.9 cw(c-1460,-1274.9) v1(-1460,-1260) C295D.1@-1460,-1245 ; U89C.1@-1474.9,-396.85 -1474.9,-374.9 cw(c-1460,-374.9) v1(-1460,-360) C295C.1@-1460,-345 ; U89B.1@-1474.9,503.15 -1474.9,525.1 cw(c-1460,525.1) v1(-1460,540) C295B.1@-1460,555 ; U89A.1@-1474.9,1403.15 -1474.9,1425.1 cw(c-1460,1425.1) v1(-1460,1440) C295A.1@-1460,1455
  Bottom Layer w20: v1(-1927.5,-1612.5) R331D.2@-1909.4,-1629.4 v1(-1894.4,-1644.4) R323D.2@-1879.4,-1659.4 ; v1(-1927.5,-712.5) R331C.2@-1909.4,-729.4 v1(-1894.4,-744.4) R323C.2@-1879.4,-759.4 ; v1(-1927.5,187.5) R331B.2@-1909.4,170.6 v1(-1894.4,155.6) R323B.2@-1879.4,140.6 ; v1(-1927.5,1087.5) R331A.2@-1909.4,1070.6 v1(-1894.4,1055.6) R323A.2@-1879.4,1040.6
  Bottom Layer w35: TP22.1@1450,-12.5 C169.2@1644.88,-12.5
